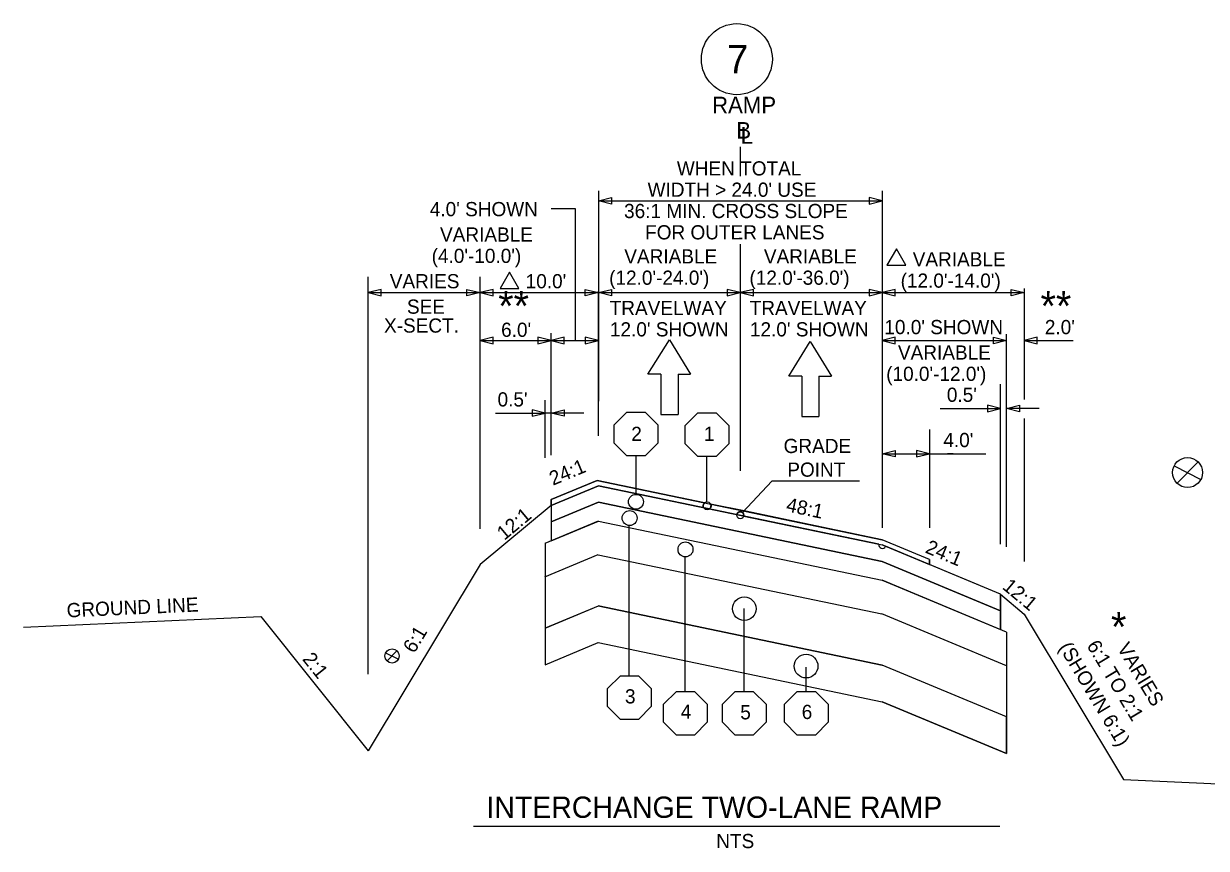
# Model space of a CAD drawing. Extents: x 4932 to 5887, y 4809 to 5473.
# Drawn here: x 5128.4 to 5228.3, y 4808.7 to 4878.4 of the extents above; entities that cross this region are included whole.
import ezdxf

# ---------------------------------------------------------------- set-up
doc = ezdxf.new("R2010")
doc.units = 0
for name, color, linetype in [('Level 20', 7, 'Continuous'), ('Level 25', 7, 'Continuous'), ('RD_QTY_Intermediate', 7, 'Continuous'), ('RD_QTY_OGFC', 7, 'Continuous'), ('RD_QTY_Surf_Course', 7, 'Continuous'), ('RD_SHT_Typical', 7, 'Continuous'), ('RD_TX_TypSect', 7, 'Continuous'), ('RD_XS_ExGround', 7, 'Continuous'), ('typical_on', 7, 'Continuous')]:
    doc.layers.add(name, color=color, linetype=linetype)

msp = doc.modelspace()

# ---------------------------------------------------------------- linework, layer by layer
at = {"layer": 'Level 20'}
for p, q in [((5181.157, 4848.747), (5182.979, 4851.662)), ((5182.979, 4851.662), (5184.763, 4848.737)), ((5193.051, 4848.585), (5194.873, 4851.5)), ((5194.873, 4851.5), (5196.657, 4848.576)), ((5182.25, 4848.747), (5181.157, 4848.747)), ((5182.25, 4848.747), (5182.25, 4845.346)), ((5183.707, 4848.737), (5184.763, 4848.737)), ((5183.707, 4848.737), (5183.707, 4845.337)), ((5194.144, 4848.585), (5193.051, 4848.585)), ((5194.144, 4848.585), (5194.144, 4845.184)), ((5195.6, 4848.576), (5196.657, 4848.576)), ((5195.6, 4848.576), (5195.6, 4845.175)), ((5182.25, 4845.346), (5183.707, 4845.337)), ((5194.144, 4845.184), (5195.6, 4845.175))]:
    msp.add_line(p, q, dxfattribs=at)
at = {"layer": 'Level 25'}
for p, q in [((5191.634, 4839.714), (5189.15, 4837.059)), ((5199.03, 4839.714), (5191.634, 4839.714))]:
    msp.add_line(p, q, dxfattribs=at)
msp.add_circle((5188.666, 4875.356), 3, dxfattribs=at)
at = {"layer": 'RD_QTY_Intermediate'}
for p, q in [((5176.962, 4837.931), (5172.964, 4836.265)), ((5200.953, 4832.933), (5176.962, 4837.931)), ((5172.964, 4834.67), (5176.962, 4836.336)), ((5172.964, 4836.265), (5172.964, 4834.67)), ((5176.962, 4836.336), (5200.953, 4831.338)), ((5210.949, 4828.768), (5200.953, 4832.933)), ((5200.953, 4831.338), (5210.949, 4827.173)), ((5210.949, 4827.173), (5210.949, 4828.768))]:
    msp.add_line(p, q, dxfattribs=at)
at = {"layer": 'RD_QTY_OGFC'}
for p, q in [((5176.852, 4839.779), (5172.964, 4838.158)), ((5172.964, 4837.661), (5176.962, 4839.327)), ((5185.946, 4837.884), (5176.852, 4839.779)), ((5176.962, 4839.327), (5185.862, 4837.473)), ((5172.964, 4838.158), (5172.964, 4837.661))]:
    msp.add_line(p, q, dxfattribs=at)
msp.add_arc((5186.156, 4837.627), 0.332, 129.19917, 207.75838, dxfattribs=at)
at = {"layer": 'RD_QTY_Surf_Course'}
for p, q in [((5176.962, 4839.327), (5172.964, 4837.661)), ((5200.659, 4834.39), (5176.962, 4839.327)), ((5172.964, 4836.265), (5176.962, 4837.931)), ((5176.962, 4837.931), (5200.953, 4832.933)), ((5172.964, 4837.661), (5172.964, 4836.265)), ((5210.949, 4830.15), (5201.23, 4834.213)), ((5200.953, 4832.933), (5210.949, 4828.768)), ((5210.949, 4828.768), (5210.949, 4830.15))]:
    msp.add_line(p, q, dxfattribs=at)
msp.add_circle((5180.142, 4837.966), 0.63, dxfattribs=at)
msp.add_arc((5200.953, 4834.329), 0.3, 168.23191, 337.31172, dxfattribs=at)
at = {"layer": 'RD_SHT_Typical'}
for p, q in [((5172.964, 4838.158), (5176.852, 4839.779)), ((5172.964, 4837.661), (5176.962, 4839.327)), ((5172.964, 4837.661), (5172.964, 4838.158)), ((5172.964, 4836.265), (5176.962, 4837.931)), ((5172.964, 4837.661), (5166.966, 4832.663)), ((5172.964, 4837.661), (5172.964, 4834.67)), ((5186.363, 4837.368), (5188.665, 4836.889)), ((5189.274, 4837.191), (5186.451, 4837.779)), ((5189.15, 4837.059), (5189.274, 4837.191)), ((5189.274, 4837.191), (5189.15, 4837.058)), ((5200.953, 4834.758), (5189.274, 4837.191)), ((5172.464, 4834.461), (5176.985, 4836.345)), ((5189.252, 4836.766), (5200.659, 4834.39)), ((5172.464, 4834.461), (5172.464, 4824.208)), ((5200.659, 4834.39), (5200.953, 4834.329)), ((5204.952, 4833.091), (5200.953, 4834.758)), ((5204.952, 4833.091), (5200.953, 4834.758)), ((5210.949, 4830.164), (5200.953, 4834.329)), ((5172.436, 4831.624), (5176.957, 4833.508)), ((5210.949, 4828.768), (5200.953, 4832.933)), ((5204.952, 4833.091), (5204.952, 4832.664)), ((5204.952, 4832.664), (5204.952, 4833.091)), ((5166.966, 4832.663), (5157.523, 4816.923)), ((5211.449, 4826.964), (5200.953, 4831.338)), ((5210.949, 4830.164), (5212.948, 4828.484)), ((5210.949, 4830.15), (5210.949, 4827.173)), ((5172.464, 4827.301), (5176.965, 4829.176)), ((5148.437, 4828.28), (5157.523, 4816.923)), ((5211.449, 4824.116), (5200.925, 4828.501)), ((5212.948, 4828.484), (5221.326, 4814.52)), ((5211.449, 4826.964), (5211.449, 4816.693)), ((5172.464, 4824.208), (5176.957, 4826.08)), ((5211.449, 4819.792), (5200.953, 4824.165)), ((5211.449, 4816.693), (5200.953, 4821.067))]:
    msp.add_line(p, q, dxfattribs=at)
for points in [[(5176.852, 4839.779), (5200.953, 4834.758)], [(5176.962, 4839.327), (5200.953, 4834.329)], [(5176.962, 4837.931), (5200.953, 4832.933)], [(5189.15, 4837.058), (5189.15, 4837.059)], [(5176.962, 4836.336), (5200.953, 4831.338)], [(5200.953, 4834.329), (5201.23, 4834.213), (5204.951, 4832.663)], [(5176.934, 4833.499), (5200.925, 4828.501)], [(5204.951, 4832.663), (5204.952, 4832.664)], [(5176.934, 4829.169), (5200.953, 4824.165)], [(5176.934, 4826.07), (5200.953, 4821.067)]]:
    msp.add_lwpolyline(points, dxfattribs=at)
for centre, radius, start, end in [((5186.156, 4837.627), 0.332, 308.70544, 27.26465), ((5188.958, 4836.828), 0.3, 50.33825, 168.23191), ((5188.958, 4836.828), 0.3, 348.23191, 50.33825)]:
    msp.add_arc(centre, radius, start, end, dxfattribs=at)
at = {"layer": 'RD_TX_TypSect'}
for p, q in [((5188.958, 4867.957), (5188.958, 4865.467)), ((5176.962, 4864.222), (5176.962, 4846.466)), ((5200.953, 4864.222), (5200.953, 4835.762)), ((5176.962, 4863.386), (5200.953, 4863.386)), ((5175.031, 4862.709), (5172.971, 4862.709)), ((5175.031, 4851.599), (5175.031, 4862.709)), ((5188.958, 4859.737), (5188.958, 4840.582)), ((5157.523, 4823.41), (5157.523, 4856.962)), ((5166.966, 4835.679), (5166.966, 4856.962)), ((5212.947, 4855.977), (5212.947, 4846.602)), ((5157.523, 4855.637), (5166.966, 4855.637)), ((5166.966, 4855.637), (5176.962, 4855.637)), ((5176.962, 4843.545), (5176.962, 4855.76)), ((5176.962, 4855.637), (5188.958, 4855.637)), ((5188.958, 4855.637), (5200.953, 4855.637)), ((5200.953, 4855.637), (5212.947, 4855.637)), ((5172.964, 4841.897), (5172.964, 4852.217)), ((5211.449, 4834.173), (5211.449, 4852.134)), ((5166.966, 4851.599), (5172.964, 4851.599)), ((5172.964, 4851.599), (5176.962, 4851.599)), ((5200.953, 4851.599), (5211.449, 4851.599)), ((5212.947, 4851.599), (5217.086, 4851.599)), ((5210.949, 4834.382), (5210.949, 4847.899)), ((5172.464, 4841.67), (5172.464, 4846.541)), ((5205.857, 4845.852), (5210.947, 4845.852)), ((5214.212, 4845.852), (5211.449, 4845.852)), ((5168.284, 4845.461), (5172.464, 4845.461)), ((5175.729, 4845.461), (5172.464, 4845.461)), ((5212.948, 4844.999), (5212.948, 4832.924)), ((5204.951, 4844.074), (5204.951, 4835.762)), ((5180.142, 4841.848), (5180.142, 4838.601)), ((5200.953, 4842.028), (5209.713, 4842.028)), ((5206.949, 4842.028), (5206.452, 4842.028)), ((5186.14, 4837.958), (5186.14, 4841.791)), ((5225.614, 4841.005), (5227.876, 4839.851)), ((5225.873, 4839.542), (5227.616, 4841.32)), ((5179.569, 4823.276), (5179.569, 4835.963)), ((5184.308, 4821.95), (5184.308, 4833.312)), ((5200.953, 4824.165), (5176.943, 4829.167)), ((5189.277, 4821.95), (5189.277, 4828.957)), ((5172.464, 4827.301), (5172.464, 4824.208)), ((5172.464, 4824.208), (5176.934, 4826.07)), ((5176.934, 4826.07), (5200.953, 4821.067)), ((5158.991, 4825.217), (5160.063, 4824.669)), ((5159.114, 4824.524), (5159.94, 4825.367)), ((5194.516, 4821.95), (5194.516, 4823.985)), ((5211.449, 4819.792), (5200.953, 4824.165)), ((5200.953, 4821.067), (5211.449, 4816.693)), ((5211.449, 4816.693), (5211.449, 4819.792)), ((5166.424, 4810.562), (5210.877, 4810.562))]:
    msp.add_line(p, q, dxfattribs=at)
for points in [[(5178.065, 4863.661), (5178.065, 4863.112), (5176.962, 4863.386)], [(5199.85, 4863.661), (5199.85, 4863.112), (5200.953, 4863.386)], [(5202.145, 4859.33), (5201.346, 4857.945), (5202.944, 4857.945)], [(5169.453, 4857.371), (5168.654, 4855.987), (5170.253, 4855.987)], [(5158.625, 4855.362), (5158.625, 4855.911), (5157.523, 4855.637)], [(5165.864, 4855.362), (5165.864, 4855.911), (5166.966, 4855.637)], [(5168.069, 4855.362), (5168.069, 4855.911), (5166.966, 4855.637)], [(5175.86, 4855.362), (5175.86, 4855.911), (5176.962, 4855.637)], [(5178.065, 4855.911), (5178.065, 4855.362), (5176.962, 4855.637)], [(5187.855, 4855.911), (5187.855, 4855.362), (5188.957, 4855.637)], [(5190.062, 4855.362), (5190.062, 4855.911), (5188.959, 4855.637)], [(5199.849, 4855.911), (5199.849, 4855.362), (5200.951, 4855.637)], [(5202.055, 4855.362), (5202.055, 4855.911), (5200.953, 4855.637)], [(5211.844, 4855.362), (5211.844, 4855.911), (5212.947, 4855.637)], [(5168.069, 4851.324), (5168.069, 4851.874), (5166.966, 4851.599)], [(5171.861, 4851.874), (5171.861, 4851.324), (5172.964, 4851.599)], [(5174.066, 4851.324), (5174.066, 4851.874), (5172.964, 4851.599)], [(5175.86, 4851.874), (5175.86, 4851.324), (5176.962, 4851.599)], [(5202.055, 4851.324), (5202.055, 4851.874), (5200.953, 4851.599)], [(5210.346, 4851.324), (5210.346, 4851.874), (5211.449, 4851.599)], [(5214.049, 4851.324), (5214.049, 4851.874), (5212.947, 4851.599)], [(5209.845, 4846.127), (5209.845, 4845.578), (5210.947, 4845.852)], [(5212.55, 4846.127), (5212.55, 4845.578), (5211.447, 4845.852)], [(5171.361, 4845.736), (5171.361, 4845.186), (5172.464, 4845.461)], [(5174.066, 4845.736), (5174.066, 4845.186), (5172.964, 4845.461)], [(5202.054, 4842.304), (5202.054, 4841.754), (5200.951, 4842.029)], [(5203.849, 4842.303), (5203.849, 4841.753), (5204.951, 4842.028)]]:
    msp.add_lwpolyline(points, close=True, dxfattribs=at)
msp.add_lwpolyline([(5176.943, 4829.167), (5176.936, 4829.164), (5172.464, 4827.301)], dxfattribs=at)
for centre, radius in [((5226.752, 4840.435), 1.265), ((5180.142, 4837.966), 0.63), ((5186.156, 4837.627), 0.332), ((5179.606, 4836.592), 0.63), ((5188.958, 4836.828), 0.3), ((5184.326, 4833.941), 0.63), ((5189.295, 4828.936), 1), ((5159.533, 4824.949), 0.6), ((5194.516, 4824.085), 1), ((5194.516, 4824.085), 1)]:
    msp.add_circle(centre, radius, dxfattribs=at)
at = {"layer": 'RD_XS_ExGround'}
for p, q in [((5128.403, 4827.367), (5148.437, 4828.28)), ((5221.326, 4814.52), (5243.416, 4813.513))]:
    msp.add_line(p, q, dxfattribs=at)
at = {"layer": 'typical_on'}
for points in [[(5181.988, 4844.459), (5181.988, 4842.929), (5180.907, 4841.848), (5179.377, 4841.848), (5178.295, 4842.929), (5178.295, 4844.459), (5179.377, 4845.54), (5180.906, 4845.54)], [(5187.987, 4844.402), (5187.987, 4842.872), (5186.905, 4841.791), (5185.376, 4841.791), (5184.294, 4842.872), (5184.294, 4844.402), (5185.375, 4845.484), (5186.905, 4845.484)], [(5181.433, 4822.194), (5181.433, 4820.664), (5180.352, 4819.583), (5178.822, 4819.583), (5177.74, 4820.664), (5177.74, 4822.194), (5178.822, 4823.276), (5180.352, 4823.276)], [(5186.172, 4820.868), (5186.172, 4819.338), (5185.091, 4818.257), (5183.561, 4818.257), (5182.48, 4819.338), (5182.479, 4820.868), (5183.561, 4821.95), (5185.091, 4821.95)], [(5191.141, 4820.868), (5191.141, 4819.338), (5190.059, 4818.257), (5188.53, 4818.257), (5187.448, 4819.338), (5187.448, 4820.868), (5188.53, 4821.95), (5190.059, 4821.95)], [(5196.38, 4820.868), (5196.38, 4819.338), (5195.299, 4818.257), (5193.769, 4818.257), (5192.688, 4819.338), (5192.688, 4820.868), (5193.769, 4821.95), (5195.299, 4821.95)]]:
    msp.add_lwpolyline(points, close=True, dxfattribs=at)

# ---------------------------------------------------------------- texts
at = {"layer": 'Level 25'}
for s, height, p in [('7', 2.4, (5187.844, 4874.156)), ('RAMP', 1.4, (5186.572, 4870.784)), ('B ', 1.4, (5188.62, 4868.645)), ('GRADE', 1.2, (5192.616, 4842.085)), ('POINT', 1.2, (5192.928, 4840.086))]:
    msp.add_text(s, height=height, dxfattribs=at).set_placement(p)
at = {"layer": 'RD_TX_TypSect'}
for s, height, p in [('L', 1.4, (5188.985, 4868.218)), ("4.0' SHOWN", 1.2, (5162.722, 4862.09)), ('VARIES', 1.2, (5159.341, 4856)), ("10.0'", 1.2, (5170.822, 4856)), ('SEE', 1.2, (5160.79, 4853.852)), ('**', 2.5, (5168.5, 4853.261)), ('**', 2.5, (5214.325, 4853.261)), ('X-SECT.', 1.2, (5158.854, 4852.255)), ("6.0'", 1.2, (5168.748, 4851.899)), ("10.0' SHOWN", 1.2, (5201.13, 4852.126)), ("2.0'", 1.2, (5214.692, 4852.126)), ("0.5'", 1.2, (5168.447, 4846.018)), ("0.5'", 1.2, (5206.411, 4846.409)), ('2', 1.2, (5179.744, 4843.104)), ('1', 1.2, (5185.885, 4843.116)), ("4.0'", 1.2, (5206.114, 4842.585)), ('*', 2.5, (5220.282, 4826.159)), ('3', 1.2, (5179.213, 4820.933)), ('4', 1.2, (5183.927, 4819.636)), ('5', 1.2, (5188.954, 4819.588)), ('6', 1.2, (5194.146, 4819.616)), ('INTERCHANGE TWO-LANE RAMP', 1.8, (5167.502, 4811.268)), ('NTS', 1.2, (5186.927, 4808.711))]:
    msp.add_text(s, height=height, dxfattribs=at).set_placement(p)
for s, rotation, p in [('WHEN TOTAL', 0.00163, (5183.596, 4865.531)), ("WIDTH > 24.0' USE", 0.00163, (5181.125, 4863.731)), ('36:1 MIN. CROSS SLOPE', 0.00163, (5179.137, 4861.931)), ('VARIABLE', 0.00163, (5163.586, 4859.943)), ('FOR OUTER LANES', 0.00163, (5180.915, 4860.131)), ("(4.0'-10.0')", 0.00163, (5162.878, 4858.143)), ('VARIABLE', 0.00163, (5179.156, 4858.097)), ('VARIABLE', 0.00163, (5190.953, 4858.097)), ('VARIABLE', 0.00163, (5203.528, 4857.851)), ("(12.0'-24.0')", 0.00163, (5177.878, 4856.297)), ("(12.0'-36.0')", 0.00163, (5189.731, 4856.297)), ("(12.0'-14.0')", 0.00163, (5202.505, 4856.051)), ('TRAVELWAY', 0.00163, (5177.92, 4853.736)), ('TRAVELWAY', 0.00163, (5189.751, 4853.736)), ("12.0' SHOWN", 0.00163, (5177.942, 4851.936)), ("12.0' SHOWN", 0.00163, (5189.772, 4851.936)), ('VARIABLE', 0.00163, (5202.28, 4849.979)), ("(10.0'-12.0')", 0.00163, (5201.286, 4848.179)), ('24:1', 22.61905, (5173.128, 4839.319)), ('48:1', 348.23171, (5192.768, 4837.167)), ('12:1', 39.80557, (5169.013, 4834.655)), ('24:1', 337.38014, (5204.511, 4833.696)), ('12:1', 320.19386, (5211.026, 4830.676)), ('GROUND LINE', 2.60954, (5132.062, 4828.194)), ('6:1', 59.03624, (5161.407, 4825.095)), ('(SHOWN 6:1)', 300.96376, (5215.834, 4825.672)), ('6:1 TO 2:1', 300.96376, (5218.188, 4825.829)), ('VARIES', 300.96376, (5220.764, 4825.617)), ('2:1', 308.65981, (5151.902, 4824.654))]:
    msp.add_text(s, height=1.2, rotation=rotation, dxfattribs=at).set_placement(p)

doc.saveas('drawing.dxf')
